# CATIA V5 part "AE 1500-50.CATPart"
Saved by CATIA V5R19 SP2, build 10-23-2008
Part number: AE 1500-50
Bounding box of the stored display mesh (mm): x -37.351 to 37.351, y -37.351 to 37.351, z 0 to 160
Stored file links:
  C:\Users\Bora\Desktop\3D Katı model\AE serisi\AE 1500\AE 1500-50.CATPart
  C:\Program Files\Dassault Systemes\B19\intel_a\reffiles\standard\MetricThickPitch.txt
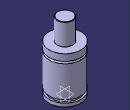
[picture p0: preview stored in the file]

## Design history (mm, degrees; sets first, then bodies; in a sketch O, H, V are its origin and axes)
Body1 (main body)
  Sketch1 on yz-plane, origin (0, 0, 0), H (0, 1, 0), V (0, 0, 1)
    point P1 (37.5, 93.5)
    point P5 (18, 159)
    point P7 (18, 159)
    point P12 (37.5, 88.5)
    point P13 (37.5, 93.5)
    point P14 (37.5, 88.5)
    line L1 (37.5, 93.5) -> (37.5, 109)
    line L2 (37.5, 0) -> (37.5, 8)
    arc A1 centre (17, 159) radius 1 from (18, 159) to (17, 160) ccw
    line L3 (18, 159) -> (18, 109)
    line L4 (33.5, 15) -> (33.5, 8)
    line L5 (37.5, 15) -> (37.5, 88.5)
    arc A2 centre (37.5, 91) radius 2.5 from (37.5, 93.5) to (37.5, 88.5) ccw
    line L6 (17, 160) -> (0, 160)
    point P15 (0, 160)
    line L7 (18, 109) -> (37.5, 109)
    line L8 (0, 0) -> (37.5, 0)
    line L9 (33.5, 15) -> (37.5, 15)
    line L10 (33.5, 8) -> (37.5, 8)
    coincidence: P15 V, P1 P13, P5 P7, P12 P14
    tangency: L6 A1
    horizontal: L7 H, L8 H, L9 H, L10 H
  Shaft1: profile Sketch1, axis Sketch1.V, angle 360
  Sketch2 on face of Shaft1 from Sketch1.L8, origin (0, 0, 0), H (1, 0, 0), V (0, -1, 0)
    point P1 (20, 0)
    distance P1 V = 20
  Hole1: placed by Sketch2, at (20, 0, 0) direction (0, 0, 1), diameter 6.647, depth 13, threaded "M8", thread diameter 8, thread depth 13, pitch 1.25
  CircPattern1: of Hole1, instances 4, angular step 90, axis from xy-plane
